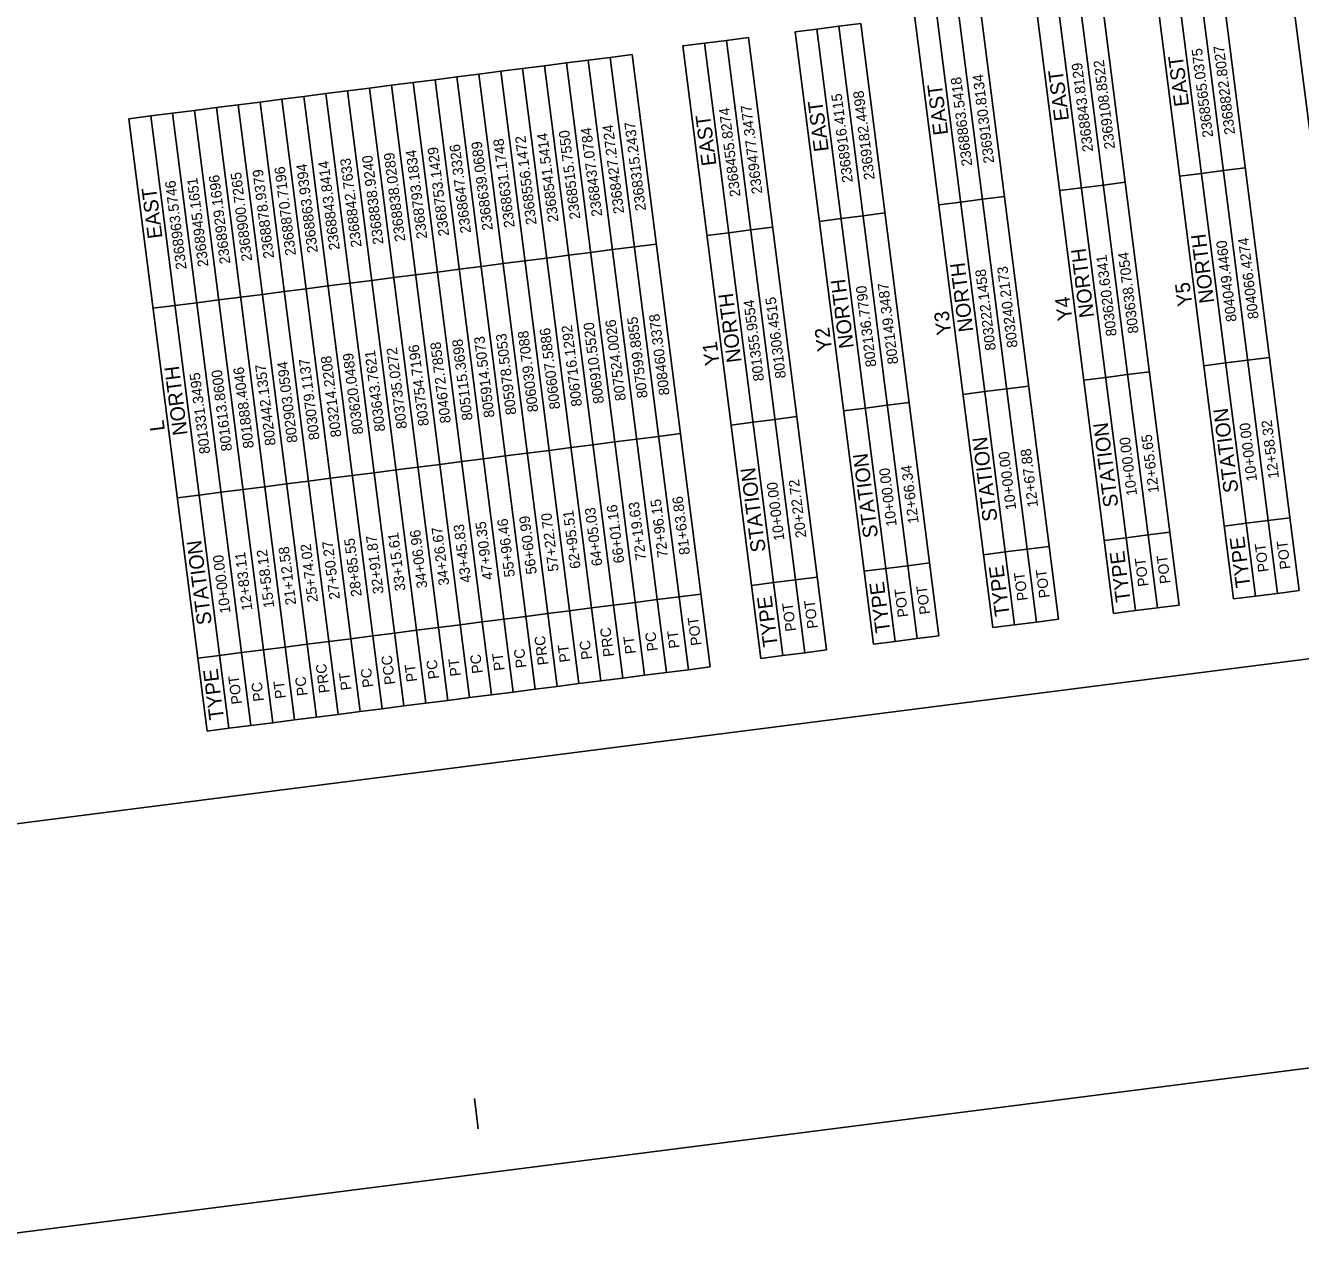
# Model space of a CAD drawing. Extents: x 2364621 to 2374814, y 792603 to 806745.
# Drawn here: x 2366733 to 2370831, y 792603 to 796538 of the extents above; entities that cross this region are included whole.
import ezdxf

# ---------------------------------------------------------------- set-up
doc = ezdxf.new("R2010")
doc.units = 0
for name, color, linetype in [('CTL Sheet Border CELL', 7, 'Continuous'), ('CTL Sheet Notes CELL', 7, 'Continuous'), ('CTL Sheet Table Cell', 7, 'Continuous'), ('CTL Sheet Text', 7, 'Continuous'), ('Scratch_Level_0', 7, 'Continuous')]:
    doc.layers.add(name, color=color, linetype=linetype)

msp = doc.modelspace()

# ---------------------------------------------------------------- linework, layer by layer
at = {"layer": 'CTL Sheet Border CELL'}
msp.add_line((2368188, 792991.4), (2368175.6, 793088.2), dxfattribs=at)
msp.add_lwpolyline([(2364831.4, 805549.1), (2366316.3, 793922.1), (2374455.2, 794961.6), (2372970.2, 806588.6)], close=True, dxfattribs=at)
at = {"layer": 'CTL Sheet Table Cell'}
for p, q in [((2370826.6, 794721.1), (2370575.2, 796689.6)), ((2371045.1, 794752.6), (2370793.6, 796721.1)), ((2370615.7, 794694.2), (2370364.3, 796662.7)), ((2370686, 794703.2), (2370434.6, 796671.7)), ((2370756.3, 794712.1), (2370504.9, 796680.6)), ((2370230, 794647.8), (2369978.6, 796616.3)), ((2370300.3, 794656.8), (2370048.9, 796625.3)), ((2370370.6, 794665.7), (2370119.2, 796634.3)), ((2370440.9, 794674.7), (2370189.5, 796643.2)), ((2369841.6, 794602), (2369590.2, 796570.5)), ((2369911.9, 794610.9), (2369660.5, 796579.5)), ((2369982.2, 794619.9), (2369730.8, 796588.4)), ((2370052.5, 794628.9), (2369801.1, 796597.4)), ((2369206.3, 796517.5), (2369276.6, 796526.5)), ((2369276.6, 796526.5), (2369346.9, 796535.5)), ((2369528.1, 794558), (2369276.6, 796526.5)), ((2369346.9, 796535.5), (2369417.3, 796544.5)), ((2369598.4, 794567), (2369346.9, 796535.5)), ((2369668.7, 794575.9), (2369417.3, 796544.5)), ((2368915.7, 796480.9), (2368986, 796489.9)), ((2368986, 796489.9), (2369056.3, 796498.9)), ((2369237.4, 794521.4), (2368986, 796489.9)), ((2369307.7, 794530.4), (2369056.3, 796498.9)), ((2369457.8, 794549), (2369206.3, 796517.5)), ((2368612, 796435.4), (2368682.3, 796444.4)), ((2368933.7, 794475.9), (2368682.3, 796444.4)), ((2368845.4, 796471.9), (2368915.7, 796480.9)), ((2369096.8, 794503.4), (2368845.4, 796471.9)), ((2369167.1, 794512.4), (2368915.7, 796480.9)), ((2368330.7, 796399.5), (2368401.1, 796408.5)), ((2368401.1, 796408.5), (2368471.4, 796417.5)), ((2368652.5, 794440), (2368401.1, 796408.5)), ((2368471.4, 796417.5), (2368541.7, 796426.5)), ((2368722.8, 794449), (2368471.4, 796417.5)), ((2368541.7, 796426.5), (2368612, 796435.4)), ((2368793.1, 794457.9), (2368541.7, 796426.5)), ((2368863.4, 794466.9), (2368612, 796435.4)), ((2367979.2, 796354.6), (2368049.5, 796363.6)), ((2368049.5, 796363.6), (2368119.8, 796372.6)), ((2368300.9, 794395.1), (2368049.5, 796363.6)), ((2368119.8, 796372.6), (2368190.1, 796381.6)), ((2368371.3, 794404.1), (2368119.8, 796372.6)), ((2368190.1, 796381.6), (2368260.4, 796390.5)), ((2368441.6, 794413), (2368190.1, 796381.6)), ((2368260.4, 796390.5), (2368330.7, 796399.5)), ((2368511.9, 794422), (2368260.4, 796390.5)), ((2368582.2, 794431), (2368330.7, 796399.5)), ((2367627.7, 796309.7), (2367698, 796318.7)), ((2367698, 796318.7), (2367768.3, 796327.7)), ((2367949.4, 794350.2), (2367698, 796318.7)), ((2367768.3, 796327.7), (2367838.6, 796336.7)), ((2368019.7, 794359.2), (2367768.3, 796327.7)), ((2367838.6, 796336.7), (2367908.9, 796345.6)), ((2368090, 794368.1), (2367838.6, 796336.7)), ((2367908.9, 796345.6), (2367979.2, 796354.6)), ((2368160.3, 794377.1), (2367908.9, 796345.6)), ((2368230.6, 794386.1), (2367979.2, 796354.6)), ((2367346.5, 796273.8), (2367416.8, 796282.8)), ((2367416.8, 796282.8), (2367487.1, 796291.8)), ((2367668.2, 794314.3), (2367416.8, 796282.8)), ((2367487.1, 796291.8), (2367557.4, 796300.7)), ((2367738.5, 794323.3), (2367487.1, 796291.8)), ((2367557.4, 796300.7), (2367627.7, 796309.7)), ((2367808.8, 794332.2), (2367557.4, 796300.7)), ((2367879.1, 794341.2), (2367627.7, 796309.7)), ((2367065.3, 796237.9), (2367135.6, 796246.9)), ((2367316.7, 794269.4), (2367065.3, 796237.9)), ((2367135.6, 796246.9), (2367205.9, 796255.8)), ((2367387, 794278.4), (2367135.6, 796246.9)), ((2367205.9, 796255.8), (2367276.2, 796264.8)), ((2367457.3, 794287.3), (2367205.9, 796255.8)), ((2367276.2, 796264.8), (2367346.5, 796273.8)), ((2367527.6, 794296.3), (2367276.2, 796264.8)), ((2367597.9, 794305.3), (2367346.5, 796273.8)), ((2370582.7, 796071.3), (2370653, 796080.3)), ((2370197, 796025), (2370267.3, 796033.9)), ((2370442.1, 796053.4), (2370512.4, 796062.4)), ((2370512.4, 796062.4), (2370582.7, 796071.3)), ((2370056.4, 796007), (2370126.7, 796016)), ((2370126.7, 796016), (2370197, 796025)), ((2369668, 795961.2), (2369738.3, 795970.2)), ((2369738.3, 795970.2), (2369808.6, 795979.1)), ((2369808.6, 795979.1), (2369878.9, 795988.1)), ((2369284.2, 795908.2), (2369354.5, 795917.2)), ((2369354.5, 795917.2), (2369424.8, 795926.2)), ((2369424.8, 795926.2), (2369495.1, 795935.2)), ((2368923.2, 795862.6), (2368993.5, 795871.6)), ((2368993.5, 795871.6), (2369063.8, 795880.6)), ((2369063.8, 795880.6), (2369134.1, 795889.6)), ((2368689.8, 795826.1), (2368760.1, 795835.1)), ((2368338.3, 795781.2), (2368408.6, 795790.2)), ((2368408.6, 795790.2), (2368478.9, 795799.2)), ((2368478.9, 795799.2), (2368549.2, 795808.2)), ((2368549.2, 795808.2), (2368619.5, 795817.2)), ((2368619.5, 795817.2), (2368689.8, 795826.1)), ((2367986.7, 795736.3), (2368057, 795745.3)), ((2368057, 795745.3), (2368127.4, 795754.3)), ((2368127.4, 795754.3), (2368197.7, 795763.3)), ((2368197.7, 795763.3), (2368268, 795772.3)), ((2368268, 795772.3), (2368338.3, 795781.2)), ((2367705.5, 795700.4), (2367775.8, 795709.4)), ((2367775.8, 795709.4), (2367846.1, 795718.4)), ((2367846.1, 795718.4), (2367916.4, 795727.4)), ((2367916.4, 795727.4), (2367986.7, 795736.3)), ((2367354, 795655.5), (2367424.3, 795664.5)), ((2367424.3, 795664.5), (2367494.6, 795673.5)), ((2367494.6, 795673.5), (2367564.9, 795682.5)), ((2367564.9, 795682.5), (2367635.2, 795691.4)), ((2367635.2, 795691.4), (2367705.5, 795700.4)), ((2367143.1, 795628.6), (2367213.4, 795637.6)), ((2367213.4, 795637.6), (2367283.7, 795646.5)), ((2367283.7, 795646.5), (2367354, 795655.5)), ((2370590.3, 795453.1), (2370660.6, 795462)), ((2370660.6, 795462), (2370730.9, 795471)), ((2370274.9, 795415.6), (2370345.2, 795424.6)), ((2370520, 795444.1), (2370590.3, 795453.1)), ((2369886.4, 795369.8), (2369956.7, 795378.8)), ((2370134.2, 795397.7), (2370204.5, 795406.7)), ((2370204.5, 795406.7), (2370274.9, 795415.6)), ((2369745.8, 795351.9), (2369816.1, 795360.9)), ((2369816.1, 795360.9), (2369886.4, 795369.8)), ((2369362, 795298.9), (2369432.3, 795307.9)), ((2369432.3, 795307.9), (2369502.6, 795316.9)), ((2369502.6, 795316.9), (2369572.9, 795325.9)), ((2369001, 795253.3), (2369071.3, 795262.3)), ((2369071.3, 795262.3), (2369141.6, 795271.3)), ((2369141.6, 795271.3), (2369211.9, 795280.3)), ((2368697.3, 795207.8), (2368767.6, 795216.8)), ((2368767.6, 795216.8), (2368837.9, 795225.8)), ((2368345.8, 795163), (2368416.1, 795171.9)), ((2368416.1, 795171.9), (2368486.4, 795180.9)), ((2368486.4, 795180.9), (2368556.7, 795189.9)), ((2368556.7, 795189.9), (2368627, 795198.9)), ((2368627, 795198.9), (2368697.3, 795207.8)), ((2368064.6, 795127), (2368134.9, 795136)), ((2368134.9, 795136), (2368205.2, 795145)), ((2368205.2, 795145), (2368275.5, 795154)), ((2368275.5, 795154), (2368345.8, 795163)), ((2367713, 795082.1), (2367783.3, 795091.1)), ((2367783.3, 795091.1), (2367853.6, 795100.1)), ((2367853.6, 795100.1), (2367924, 795109.1)), ((2367924, 795109.1), (2367994.3, 795118.1)), ((2367994.3, 795118.1), (2368064.6, 795127)), ((2367431.8, 795046.2), (2367502.1, 795055.2)), ((2367502.1, 795055.2), (2367572.4, 795064.2)), ((2367572.4, 795064.2), (2367642.7, 795073.2)), ((2367642.7, 795073.2), (2367713, 795082.1)), ((2367220.9, 795019.3), (2367291.2, 795028.3)), ((2367291.2, 795028.3), (2367361.5, 795037.2)), ((2367361.5, 795037.2), (2367431.8, 795046.2)), ((2370585.8, 794928.5), (2370656.1, 794937.5)), ((2370656.1, 794937.5), (2370726.4, 794946.5)), ((2370726.4, 794946.5), (2370796.7, 794955.5)), ((2370200.1, 794882.1), (2370270.4, 794891.1)), ((2370270.4, 794891.1), (2370340.7, 794900.1)), ((2370340.7, 794900.1), (2370411, 794909.1)), ((2369811.7, 794836.3), (2369882, 794845.3)), ((2369882, 794845.3), (2369952.3, 794854.3)), ((2369952.3, 794854.3), (2370022.6, 794863.2)), ((2369568.4, 794801.3), (2369638.7, 794810.3)), ((2369207.5, 794755.7), (2369277.8, 794764.7)), ((2369427.8, 794783.4), (2369498.1, 794792.3)), ((2369498.1, 794792.3), (2369568.4, 794801.3)), ((2369066.9, 794737.8), (2369137.2, 794746.7)), ((2369137.2, 794746.7), (2369207.5, 794755.7)), ((2370756.3, 794712.1), (2370826.6, 794721.1)), ((2368622.5, 794674.3), (2368692.8, 794683.3)), ((2368692.8, 794683.3), (2368763.1, 794692.3)), ((2368763.1, 794692.3), (2368833.4, 794701.3)), ((2368833.4, 794701.3), (2368903.8, 794710.2)), ((2370615.7, 794694.2), (2370686, 794703.2)), ((2370686, 794703.2), (2370756.3, 794712.1)), ((2368271, 794629.4), (2368341.3, 794638.4)), ((2368341.3, 794638.4), (2368411.6, 794647.4)), ((2368411.6, 794647.4), (2368481.9, 794656.4)), ((2368481.9, 794656.4), (2368552.2, 794665.4)), ((2368552.2, 794665.4), (2368622.5, 794674.3)), ((2370230, 794647.8), (2370300.3, 794656.8)), ((2370300.3, 794656.8), (2370370.6, 794665.7)), ((2370370.6, 794665.7), (2370440.9, 794674.7)), ((2367989.8, 794593.5), (2368060.1, 794602.5)), ((2368060.1, 794602.5), (2368130.4, 794611.5)), ((2368130.4, 794611.5), (2368200.7, 794620.5)), ((2368200.7, 794620.5), (2368271, 794629.4)), ((2369841.6, 794602), (2369911.9, 794610.9)), ((2369911.9, 794610.9), (2369982.2, 794619.9)), ((2369982.2, 794619.9), (2370052.5, 794628.9)), ((2367638.3, 794548.6), (2367708.6, 794557.6)), ((2367708.6, 794557.6), (2367778.9, 794566.6)), ((2367778.9, 794566.6), (2367849.2, 794575.6)), ((2367849.2, 794575.6), (2367919.5, 794584.5)), ((2367919.5, 794584.5), (2367989.8, 794593.5)), ((2369457.8, 794549), (2369528.1, 794558)), ((2369528.1, 794558), (2369598.4, 794567)), ((2369598.4, 794567), (2369668.7, 794575.9)), ((2367357.1, 794512.7), (2367427.4, 794521.7)), ((2367427.4, 794521.7), (2367497.7, 794530.7)), ((2367497.7, 794530.7), (2367568, 794539.6)), ((2367568, 794539.6), (2367638.3, 794548.6)), ((2369167.1, 794512.4), (2369237.4, 794521.4)), ((2369237.4, 794521.4), (2369307.7, 794530.4)), ((2367286.8, 794503.7), (2367357.1, 794512.7)), ((2368863.4, 794466.9), (2368933.7, 794475.9)), ((2369096.8, 794503.4), (2369167.1, 794512.4)), ((2368582.2, 794431), (2368652.5, 794440)), ((2368652.5, 794440), (2368722.8, 794449)), ((2368722.8, 794449), (2368793.1, 794457.9)), ((2368793.1, 794457.9), (2368863.4, 794466.9)), ((2368230.6, 794386.1), (2368300.9, 794395.1)), ((2368300.9, 794395.1), (2368371.3, 794404.1)), ((2368371.3, 794404.1), (2368441.6, 794413)), ((2368441.6, 794413), (2368511.9, 794422)), ((2368511.9, 794422), (2368582.2, 794431)), ((2367949.4, 794350.2), (2368019.7, 794359.2)), ((2368019.7, 794359.2), (2368090, 794368.1)), ((2368090, 794368.1), (2368160.3, 794377.1)), ((2368160.3, 794377.1), (2368230.6, 794386.1)), ((2367597.9, 794305.3), (2367668.2, 794314.3)), ((2367668.2, 794314.3), (2367738.5, 794323.3)), ((2367738.5, 794323.3), (2367808.8, 794332.2)), ((2367808.8, 794332.2), (2367879.1, 794341.2)), ((2367879.1, 794341.2), (2367949.4, 794350.2)), ((2367316.7, 794269.4), (2367387, 794278.4)), ((2367387, 794278.4), (2367457.3, 794287.3)), ((2367457.3, 794287.3), (2367527.6, 794296.3)), ((2367527.6, 794296.3), (2367597.9, 794305.3))]:
    msp.add_line(p, q, dxfattribs=at)
at = {"layer": 'Scratch_Level_0'}
msp.add_lwpolyline([(2374814.3, 793692), (2373147.1, 806745.2), (2364620.8, 805656.2), (2366287.9, 792603)], close=True, dxfattribs=at)

# ---------------------------------------------------------------- texts
at = {"layer": 'CTL Sheet Notes CELL'}
for s, height, p in [('EAST', 47.25, (2370472.7, 796280.3)), ('EAST', 47.25, (2370087, 796233.9)), ('EAST', 47.25, (2369698.6, 796188.1)), ('EAST', 47.25, (2369314.7, 796135.1)), ('EAST', 47.25, (2368953.8, 796089.5)), ('EAST', 47.25, (2367173.7, 795855.5)), ('NORTH', 47.25, (2370553.5, 795647.7)), ('NORTH', 47.25, (2370167.8, 795601.3)), ('NORTH', 47.25, (2369779.4, 795555.5)), ('NORTH', 47.25, (2369395.5, 795502.5)), ('Y5', 47.25, (2370483.3, 795638.2)), ('NORTH', 47.25, (2369034.5, 795457)), ('Y4', 47.25, (2370097.5, 795591.8)), ('Y3', 47.25, (2369709.1, 795546)), ('Y2', 47.25, (2369325.3, 795493)), ('Y1', 47.25, (2368964.3, 795447.4)), ('NORTH', 47.25, (2367254.4, 795222.9)), ('STATION', 47.25, (2370631.3, 795038.8)), ('L', 47.2, (2367181.2, 795236.6)), ('STATION', 47.25, (2370245.5, 794992.4)), ('STATION', 47.25, (2369857.1, 794946.6)), ('STATION', 47.25, (2369473.3, 794893.6)), ('STATION', 47.25, (2369112.3, 794848)), ('TYPE', 47.25, (2370670.2, 794733.6)), ('STATION', 47.25, (2367332.2, 794614)), ('TYPE', 47.25, (2370284.5, 794687.2)), ('TYPE', 47.25, (2369896.1, 794641.4)), ('TYPE', 47.25, (2369512.3, 794588.4)), ('TYPE', 47.25, (2369151.3, 794542.8)), ('TYPE', 47.25, (2367371.2, 794308.8))]:
    msp.add_text(s, height=height, rotation=97.2784, dxfattribs=at).set_placement(p)
at = {"layer": 'CTL Sheet Text'}
for s, p in [('2368565.0375', (2370550.2, 796179.9)), ('2368822.8027', (2370620.5, 796188.9)), ('2368843.8129', (2370164.5, 796133.5)), ('2369108.8522', (2370234.8, 796142.5)), ('2368863.5418', (2369776, 796087.7)), ('2369130.8134', (2369846.4, 796096.7)), ('2368916.4115', (2369392.2, 796034.7)), ('2369182.4498', (2369462.5, 796043.7)), ('2369477.3477', (2369101.5, 795998.1)), ('2368455.8274', (2369031.2, 795989.1)), ('2368515.7550', (2368516.6, 795916.7)), ('2368437.0784', (2368586.9, 795925.7)), ('2368427.2724', (2368657.2, 795934.7)), ('2368315.2437', (2368727.5, 795943.7)), ('2368647.3326', (2368165.1, 795871.8)), ('2368639.0689', (2368235.4, 795880.8)), ('2368631.1748', (2368305.7, 795889.8)), ('2368556.1472', (2368376, 795898.8)), ('2368541.5414', (2368446.3, 795907.7)), ('2368838.9240', (2367883.9, 795835.9)), ('2368838.0289', (2367954.2, 795844.9)), ('2368793.1834', (2368024.5, 795853.9)), ('2368753.1429', (2368094.8, 795862.8)), ('2368878.9379', (2367532.3, 795791)), ('2368870.7196', (2367602.6, 795800)), ('2368863.9394', (2367672.9, 795809)), ('2368843.8414', (2367743.3, 795817.9)), ('2368842.7633', (2367813.6, 795826.9)), ('2368963.5746', (2367251.1, 795755.1)), ('2368945.1651', (2367321.4, 795764.1)), ('2368929.1696', (2367391.7, 795773.1)), ('2368900.7265', (2367462, 795782)), ('804049.4460', (2370625.9, 795587.2)), ('804066.4274', (2370696.2, 795596.2)), ('803620.6341', (2370240.2, 795540.8)), ('803638.7054', (2370310.5, 795549.8)), ('803222.1458', (2369851.7, 795495)), ('803240.2173', (2369922.1, 795504)), ('802149.3487', (2369538.2, 795451)), ('801306.4515', (2369177.2, 795405.4)), ('802136.7790', (2369467.9, 795442)), ('801355.9554', (2369106.9, 795396.4)), ('806910.5520', (2368592.3, 795324)), ('807524.0026', (2368662.6, 795333)), ('807599.8855', (2368732.9, 795342)), ('808460.3378', (2368803.2, 795351)), ('805978.5053', (2368311.1, 795288.1)), ('806039.7088', (2368381.4, 795297.1)), ('806607.5886', (2368451.7, 795306.1)), ('806716.1292', (2368522, 795315)), ('803735.0272', (2367959.6, 795243.2)), ('803754.7196', (2368029.9, 795252.2)), ('804672.7858', (2368100.2, 795261.2)), ('805115.3698', (2368170.5, 795270.2)), ('805914.5073', (2368240.8, 795279.1)), ('803079.1137', (2367678.3, 795207.3)), ('803214.2208', (2367748.6, 795216.3)), ('803620.0489', (2367819, 795225.3)), ('803643.7621', (2367889.3, 795234.2)), ('801331.3495', (2367326.8, 795162.4)), ('801613.8600', (2367397.1, 795171.4)), ('801888.4046', (2367467.4, 795180.4)), ('802442.1357', (2367537.7, 795189.3)), ('802903.0594', (2367608, 795198.3)), ('10+00.00', (2370691.3, 795074.6)), ('12+58.32', (2370761.6, 795083.6)), ('10+00.00', (2370305.6, 795028.2)), ('12+65.65', (2370375.9, 795037.2)), ('12+67.88', (2369987.5, 794991.4)), ('10+00.00', (2369917.2, 794982.4)), ('10+00.00', (2369533.4, 794929.4)), ('12+66.34', (2369603.7, 794938.4)), ('10+00.00', (2369172.4, 794883.8)), ('20+22.72', (2369242.7, 794892.8)), ('72+96.15', (2368798.4, 794829.4)), ('81+63.86', (2368868.7, 794838.4)), ('57+22.70', (2368446.9, 794784.5)), ('62+95.51', (2368517.2, 794793.5)), ('64+05.03', (2368587.5, 794802.4)), ('66+01.16', (2368657.8, 794811.4)), ('72+19.63', (2368728.1, 794820.4)), ('43+45.83', (2368165.6, 794748.6)), ('47+90.35', (2368235.9, 794757.5)), ('55+96.46', (2368306.2, 794766.5)), ('56+60.99', (2368376.5, 794775.5)), ('28+85.55', (2367814.1, 794703.7)), ('32+91.87', (2367884.4, 794712.6)), ('33+15.61', (2367954.7, 794721.6)), ('34+06.96', (2368025, 794730.6)), ('34+26.67', (2368095.3, 794739.6)), ('12+83.11', (2367462.6, 794658.8)), ('15+58.12', (2367532.9, 794667.7)), ('21+12.58', (2367603.2, 794676.7)), ('25+74.02', (2367673.5, 794685.7)), ('27+50.27', (2367743.8, 794694.7)), ('POT', (2370728.6, 794782.7)), ('POT', (2370798.9, 794791.7)), ('10+00.00', (2367392.3, 794649.8)), ('POT', (2370342.9, 794736.3)), ('POT', (2370413.2, 794745.3)), ('POT', (2369954.5, 794690.5)), ('POT', (2370024.8, 794699.4)), ('POT', (2369570.6, 794637.5)), ('POT', (2369640.9, 794646.5)), ('POT', (2369209.7, 794591.9)), ('POT', (2369280, 794600.9)), ('PRC', (2368624.7, 794510.5)), ('POT', (2368906, 794546.4)), ('PRC', (2368413.8, 794483.6)), ('PC ', (2368554.4, 794501.5)), ('PT ', (2368695, 794519.5)), ('PC ', (2368765.4, 794528.5)), ('PT ', (2368835.7, 794537.5)), ('PC ', (2368202.9, 794456.6)), ('PT ', (2368273.2, 794465.6)), ('PC ', (2368343.5, 794474.6)), ('PT ', (2368484.1, 794492.6)), ('PRC', (2367710.8, 794393.8)), ('PCC', (2367921.7, 794420.7)), ('PT ', (2367992, 794429.7)), ('PC ', (2368062.3, 794438.7)), ('PT ', (2368132.6, 794447.7)), ('POT', (2367429.6, 794357.9)), ('PC ', (2367640.5, 794384.8)), ('PT ', (2367781.1, 794402.8)), ('PC ', (2367851.4, 794411.7)), ('PC ', (2367499.9, 794366.9)), ('PT ', (2367570.2, 794375.8))]:
    msp.add_text(s, height=33.75, rotation=97.2784, dxfattribs=at).set_placement(p)

doc.saveas('drawing.dxf')
